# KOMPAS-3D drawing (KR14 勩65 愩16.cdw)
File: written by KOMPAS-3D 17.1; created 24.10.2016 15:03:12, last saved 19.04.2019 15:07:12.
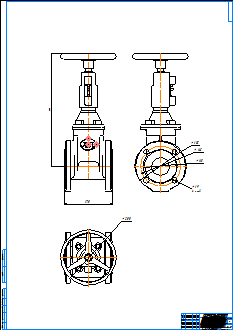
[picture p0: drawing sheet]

Sheet 1: A0, portrait

Title block, sheet 1: name: KR14 Ду65 Ру16; material: Внимание! Данный продукт является объектом авторского права ООО «Торговый Дом АДЛ». / Запрещается изменение, копирование, распространение / (в том числе путем копирования на другие сайты и ресурсы в Интернете) / или любое иное использование информации и объектов без предварительного / согласия правообладателя (ООО «Торговый Дом АДЛ»).; mass: 27,9; sheets: 1; organisation: ООО "Торговый дом АДЛ"; sheet format: A0; stored path: \\adlc.lan\data\АДЛ_ПКД\3D-модели\ADL production\Клиновые задвижки серии KR ГРАНАР\Клиновые задвижки KR14\kompas 2d\KR14 Ду65 Ру16.cdw

Views: Вид 1
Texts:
  Klimkovich
  ADL
Dimensions and other numbers on the sheet: 170; 405; 1:1; 1; 27,9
